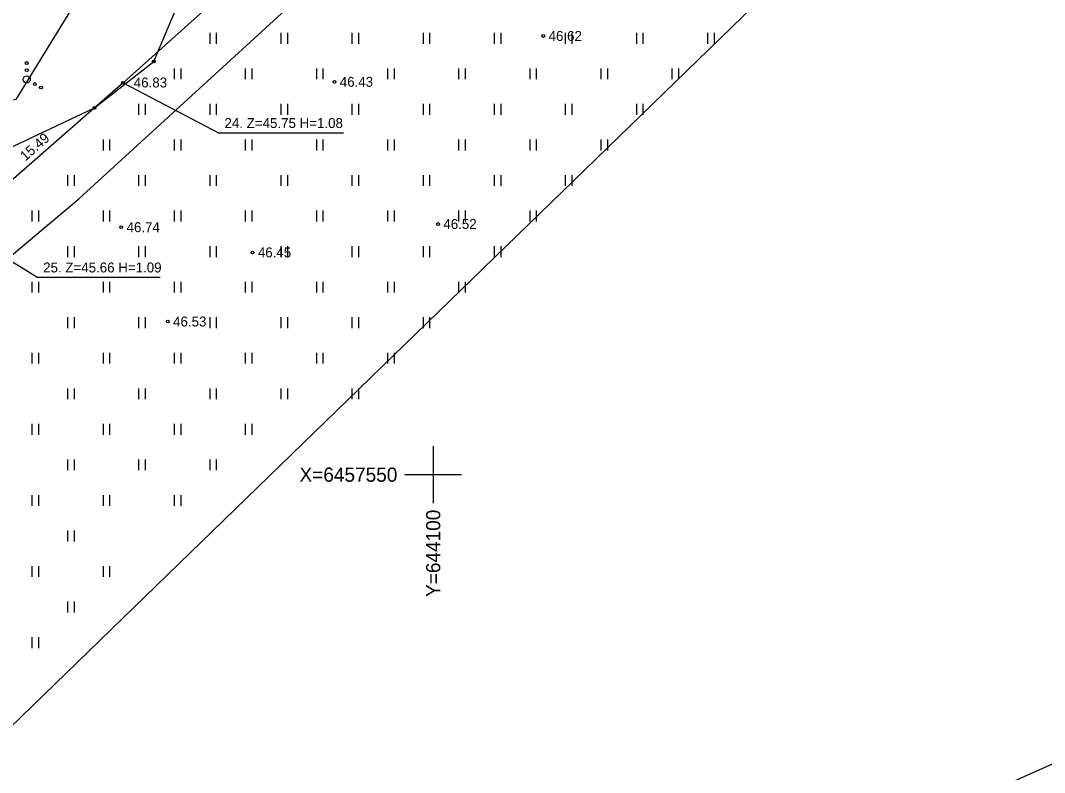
# Model space of a CAD drawing. Extents: x 642747 to 644424, y 6457048 to 6458238.
# Drawn here: x 644071 to 644143, y 6457529.1 to 6457581.9 of the extents above; entities that cross this region are included whole.
import ezdxf

# ---------------------------------------------------------------- set-up
doc = ezdxf.new("R2010")
doc.units = 0
for name, color, linetype in [('HALJASTUS', 7, 'Continuous'), ('JOONSIDE', 7, 'Continuous'), ('KOORDPUNKT', 7, 'Continuous'), ('KORGUS', 7, 'Continuous'), ('KPKAABEL', 7, 'Continuous'), ('MOOTPIIR', 7, 'Continuous'), ('TEE', 7, 'Continuous'), ('VORK', 7, 'Continuous'), ('VORMISTUS', 7, 'Continuous')]:
    doc.layers.add(name, color=color, linetype=linetype)

msp = doc.modelspace()

# ---------------------------------------------------------------- linework, layer by layer
at = {"layer": 'HALJASTUS'}
for p, q in [((644084.29, 6457581.069), (644084.29, 6457580.307)), ((644084.745, 6457581.069), (644084.745, 6457580.307)), ((644089.29, 6457581.069), (644089.29, 6457580.307)), ((644089.745, 6457581.069), (644089.745, 6457580.307)), ((644094.29, 6457581.069), (644094.29, 6457580.307)), ((644094.745, 6457581.069), (644094.745, 6457580.307)), ((644099.29, 6457581.069), (644099.29, 6457580.307)), ((644099.745, 6457581.069), (644099.745, 6457580.307)), ((644104.29, 6457581.069), (644104.29, 6457580.307)), ((644104.745, 6457581.069), (644104.745, 6457580.307)), ((644109.29, 6457581.069), (644109.29, 6457580.307)), ((644109.745, 6457581.069), (644109.745, 6457580.307)), ((644114.29, 6457581.069), (644114.29, 6457580.307)), ((644114.745, 6457581.069), (644114.745, 6457580.307)), ((644119.29, 6457581.069), (644119.29, 6457580.307)), ((644119.745, 6457581.069), (644119.745, 6457580.307)), ((644081.79, 6457578.569), (644081.79, 6457577.807)), ((644082.245, 6457578.569), (644082.245, 6457577.807)), ((644086.79, 6457578.569), (644086.79, 6457577.807)), ((644087.245, 6457578.569), (644087.245, 6457577.807)), ((644091.79, 6457578.569), (644091.79, 6457577.807)), ((644092.245, 6457578.569), (644092.245, 6457577.807)), ((644096.79, 6457578.569), (644096.79, 6457577.807)), ((644097.245, 6457578.569), (644097.245, 6457577.807)), ((644101.79, 6457578.569), (644101.79, 6457577.807)), ((644102.245, 6457578.569), (644102.245, 6457577.807)), ((644106.79, 6457578.569), (644106.79, 6457577.807)), ((644107.245, 6457578.569), (644107.245, 6457577.807)), ((644111.79, 6457578.569), (644111.79, 6457577.807)), ((644112.245, 6457578.569), (644112.245, 6457577.807)), ((644116.79, 6457578.569), (644116.79, 6457577.807)), ((644117.245, 6457578.569), (644117.245, 6457577.807)), ((644079.29, 6457576.069), (644079.29, 6457575.307)), ((644079.745, 6457576.069), (644079.745, 6457575.307)), ((644084.29, 6457576.069), (644084.29, 6457575.307)), ((644084.745, 6457576.069), (644084.745, 6457575.307)), ((644089.29, 6457576.069), (644089.29, 6457575.307)), ((644089.745, 6457576.069), (644089.745, 6457575.307)), ((644094.29, 6457576.069), (644094.29, 6457575.307)), ((644094.745, 6457576.069), (644094.745, 6457575.307)), ((644099.29, 6457576.069), (644099.29, 6457575.307)), ((644099.745, 6457576.069), (644099.745, 6457575.307)), ((644104.29, 6457576.069), (644104.29, 6457575.307)), ((644104.745, 6457576.069), (644104.745, 6457575.307)), ((644109.29, 6457576.069), (644109.29, 6457575.307)), ((644109.745, 6457576.069), (644109.745, 6457575.307)), ((644114.29, 6457576.069), (644114.29, 6457575.307)), ((644114.745, 6457576.069), (644114.745, 6457575.307)), ((644076.79, 6457573.569), (644076.79, 6457572.807)), ((644077.245, 6457573.569), (644077.245, 6457572.807)), ((644081.79, 6457573.569), (644081.79, 6457572.807)), ((644082.245, 6457573.569), (644082.245, 6457572.807)), ((644086.79, 6457573.569), (644086.79, 6457572.807)), ((644087.245, 6457573.569), (644087.245, 6457572.807)), ((644091.79, 6457573.569), (644091.79, 6457572.807)), ((644092.245, 6457573.569), (644092.245, 6457572.807)), ((644096.79, 6457573.569), (644096.79, 6457572.807)), ((644097.245, 6457573.569), (644097.245, 6457572.807)), ((644101.79, 6457573.569), (644101.79, 6457572.807)), ((644102.245, 6457573.569), (644102.245, 6457572.807)), ((644106.79, 6457573.569), (644106.79, 6457572.807)), ((644107.245, 6457573.569), (644107.245, 6457572.807)), ((644111.79, 6457573.569), (644111.79, 6457572.807)), ((644112.245, 6457573.569), (644112.245, 6457572.807)), ((644074.29, 6457571.069), (644074.29, 6457570.307)), ((644074.745, 6457571.069), (644074.745, 6457570.307)), ((644079.29, 6457571.069), (644079.29, 6457570.307)), ((644079.745, 6457571.069), (644079.745, 6457570.307)), ((644084.29, 6457571.069), (644084.29, 6457570.307)), ((644084.745, 6457571.069), (644084.745, 6457570.307)), ((644089.29, 6457571.069), (644089.29, 6457570.307)), ((644089.745, 6457571.069), (644089.745, 6457570.307)), ((644094.29, 6457571.069), (644094.29, 6457570.307)), ((644094.745, 6457571.069), (644094.745, 6457570.307)), ((644099.29, 6457571.069), (644099.29, 6457570.307)), ((644099.745, 6457571.069), (644099.745, 6457570.307)), ((644104.29, 6457571.069), (644104.29, 6457570.307)), ((644104.745, 6457571.069), (644104.745, 6457570.307)), ((644109.29, 6457571.069), (644109.29, 6457570.307)), ((644109.745, 6457571.069), (644109.745, 6457570.307)), ((644071.79, 6457568.569), (644071.79, 6457567.807)), ((644072.245, 6457568.569), (644072.245, 6457567.807)), ((644076.79, 6457568.569), (644076.79, 6457567.807)), ((644077.245, 6457568.569), (644077.245, 6457567.807)), ((644081.79, 6457568.569), (644081.79, 6457567.807)), ((644082.245, 6457568.569), (644082.245, 6457567.807)), ((644086.79, 6457568.569), (644086.79, 6457567.807)), ((644087.245, 6457568.569), (644087.245, 6457567.807)), ((644091.79, 6457568.569), (644091.79, 6457567.807)), ((644092.245, 6457568.569), (644092.245, 6457567.807)), ((644096.79, 6457568.569), (644096.79, 6457567.807)), ((644097.245, 6457568.569), (644097.245, 6457567.807)), ((644101.79, 6457568.569), (644101.79, 6457567.807)), ((644102.245, 6457568.569), (644102.245, 6457567.807)), ((644106.79, 6457568.569), (644106.79, 6457567.807)), ((644107.245, 6457568.569), (644107.245, 6457567.807)), ((644074.29, 6457566.069), (644074.29, 6457565.307)), ((644074.745, 6457566.069), (644074.745, 6457565.307)), ((644079.29, 6457566.069), (644079.29, 6457565.307)), ((644079.745, 6457566.069), (644079.745, 6457565.307)), ((644084.29, 6457566.069), (644084.29, 6457565.307)), ((644084.745, 6457566.069), (644084.745, 6457565.307)), ((644089.29, 6457566.069), (644089.29, 6457565.307)), ((644089.745, 6457566.069), (644089.745, 6457565.307)), ((644094.29, 6457566.069), (644094.29, 6457565.307)), ((644094.745, 6457566.069), (644094.745, 6457565.307)), ((644099.29, 6457566.069), (644099.29, 6457565.307)), ((644099.745, 6457566.069), (644099.745, 6457565.307)), ((644104.29, 6457566.069), (644104.29, 6457565.307)), ((644104.745, 6457566.069), (644104.745, 6457565.307)), ((644071.79, 6457563.569), (644071.79, 6457562.807)), ((644072.245, 6457563.569), (644072.245, 6457562.807)), ((644076.79, 6457563.569), (644076.79, 6457562.807)), ((644077.245, 6457563.569), (644077.245, 6457562.807)), ((644081.79, 6457563.569), (644081.79, 6457562.807)), ((644082.245, 6457563.569), (644082.245, 6457562.807)), ((644086.79, 6457563.569), (644086.79, 6457562.807)), ((644087.245, 6457563.569), (644087.245, 6457562.807)), ((644091.79, 6457563.569), (644091.79, 6457562.807)), ((644092.245, 6457563.569), (644092.245, 6457562.807)), ((644096.79, 6457563.569), (644096.79, 6457562.807)), ((644097.245, 6457563.569), (644097.245, 6457562.807)), ((644101.79, 6457563.569), (644101.79, 6457562.807)), ((644102.245, 6457563.569), (644102.245, 6457562.807)), ((644074.29, 6457561.069), (644074.29, 6457560.307)), ((644074.745, 6457561.069), (644074.745, 6457560.307)), ((644079.29, 6457561.069), (644079.29, 6457560.307)), ((644079.745, 6457561.069), (644079.745, 6457560.307)), ((644084.29, 6457561.069), (644084.29, 6457560.307)), ((644084.745, 6457561.069), (644084.745, 6457560.307)), ((644089.29, 6457561.069), (644089.29, 6457560.307)), ((644089.745, 6457561.069), (644089.745, 6457560.307)), ((644094.29, 6457561.069), (644094.29, 6457560.307)), ((644094.745, 6457561.069), (644094.745, 6457560.307)), ((644099.29, 6457561.069), (644099.29, 6457560.307)), ((644099.745, 6457561.069), (644099.745, 6457560.307)), ((644071.79, 6457558.569), (644071.79, 6457557.807)), ((644072.245, 6457558.569), (644072.245, 6457557.807)), ((644076.79, 6457558.569), (644076.79, 6457557.807)), ((644077.245, 6457558.569), (644077.245, 6457557.807)), ((644081.79, 6457558.569), (644081.79, 6457557.807)), ((644082.245, 6457558.569), (644082.245, 6457557.807)), ((644086.79, 6457558.569), (644086.79, 6457557.807)), ((644087.245, 6457558.569), (644087.245, 6457557.807)), ((644091.79, 6457558.569), (644091.79, 6457557.807)), ((644092.245, 6457558.569), (644092.245, 6457557.807)), ((644096.79, 6457558.569), (644096.79, 6457557.807)), ((644097.245, 6457558.569), (644097.245, 6457557.807)), ((644074.29, 6457556.069), (644074.29, 6457555.307)), ((644074.745, 6457556.069), (644074.745, 6457555.307)), ((644079.29, 6457556.069), (644079.29, 6457555.307)), ((644079.745, 6457556.069), (644079.745, 6457555.307)), ((644084.29, 6457556.069), (644084.29, 6457555.307)), ((644084.745, 6457556.069), (644084.745, 6457555.307)), ((644089.29, 6457556.069), (644089.29, 6457555.307)), ((644089.745, 6457556.069), (644089.745, 6457555.307)), ((644094.29, 6457556.069), (644094.29, 6457555.307)), ((644094.745, 6457556.069), (644094.745, 6457555.307)), ((644071.79, 6457553.569), (644071.79, 6457552.807)), ((644072.245, 6457553.569), (644072.245, 6457552.807)), ((644076.79, 6457553.569), (644076.79, 6457552.807)), ((644077.245, 6457553.569), (644077.245, 6457552.807)), ((644081.79, 6457553.569), (644081.79, 6457552.807)), ((644082.245, 6457553.569), (644082.245, 6457552.807)), ((644086.79, 6457553.569), (644086.79, 6457552.807)), ((644087.245, 6457553.569), (644087.245, 6457552.807)), ((644074.29, 6457551.069), (644074.29, 6457550.307)), ((644074.745, 6457551.069), (644074.745, 6457550.307)), ((644079.29, 6457551.069), (644079.29, 6457550.307)), ((644079.745, 6457551.069), (644079.745, 6457550.307)), ((644084.29, 6457551.069), (644084.29, 6457550.307)), ((644084.745, 6457551.069), (644084.745, 6457550.307)), ((644071.79, 6457548.569), (644071.79, 6457547.807)), ((644072.245, 6457548.569), (644072.245, 6457547.807)), ((644076.79, 6457548.569), (644076.79, 6457547.807)), ((644077.245, 6457548.569), (644077.245, 6457547.807)), ((644081.79, 6457548.569), (644081.79, 6457547.807)), ((644082.245, 6457548.569), (644082.245, 6457547.807)), ((644074.29, 6457546.069), (644074.29, 6457545.307)), ((644074.745, 6457546.069), (644074.745, 6457545.307)), ((644071.79, 6457543.569), (644071.79, 6457542.807)), ((644072.245, 6457543.569), (644072.245, 6457542.807)), ((644076.79, 6457543.569), (644076.79, 6457542.807)), ((644077.245, 6457543.569), (644077.245, 6457542.807)), ((644074.29, 6457541.069), (644074.29, 6457540.307)), ((644074.745, 6457541.069), (644074.745, 6457540.307)), ((644071.79, 6457538.569), (644071.79, 6457537.807)), ((644072.245, 6457538.569), (644072.245, 6457537.807))]:
    msp.add_line(p, q, dxfattribs=at)
msp.add_lwpolyline([(644041.809, 6457571.148), (644051.359, 6457564.407), (644056.959, 6457566.734), (644063.59, 6457569.91), (644069.17, 6457572.488), (644076.19, 6457575.794), (644080.356, 6457579.056), (644082.641, 6457584.464), (644086.464, 6457590.743), (644093.515, 6457598.78), (644095.215, 6457603.14), (644095.047, 6457607.095)], dxfattribs=at)
for centre, radius in [((644071.422, 6457578.949), 0.1), ((644071.422, 6457577.799), 0.25), ((644071.422, 6457578.449), 0.1), ((644071.987, 6457577.474), 0.1), ((644072.422, 6457577.224), 0.1)]:
    msp.add_circle(centre, radius, dxfattribs=at)
at = {"layer": 'KOORDPUNKT'}
for p, q in [((644078.192, 6457577.561), (644084.942, 6457574.027)), ((644093.691, 6457574.027), (644084.942, 6457574.027)), ((644066.524, 6457567.369), (644072.19, 6457563.871)), ((644080.799, 6457563.871), (644072.19, 6457563.871))]:
    msp.add_line(p, q, dxfattribs=at)
msp.add_lwpolyline([(644078.192, 6457577.561), (644078.192, 6457577.561), (644078.192, 6457577.561)], dxfattribs=at)
at = {"layer": 'KORGUS'}
for centre in [(644107.738, 6457580.854), (644080.356, 6457579.056), (644078.192, 6457577.561), (644093.057, 6457577.629), (644076.19, 6457575.794), (644078.065, 6457567.404), (644100.342, 6457567.628), (644087.299, 6457565.629), (644081.337, 6457560.771)]:
    msp.add_circle(centre, 0.1, dxfattribs=at)
at = {"layer": 'KPKAABEL'}
msp.add_lwpolyline([(644103.079, 6457652.715), (644111.131, 6457630.665), (644117.872, 6457612.305), (644117.831, 6457611.89), (644117.527, 6457611.592), (644112.751, 6457607.616), (644102.693, 6457600.124), (644092.698, 6457590.582), (644078.192, 6457577.561), (644066.524, 6457567.369), (644056.896, 6457559.139), (644048.865, 6457552.537), (644048.039, 6457551.927), (644047.155, 6457551.979), (644039.639, 6457557.844), (644029.553, 6457566.384), (644016.901, 6457577.396), (644002.145, 6457590.823), (643989.718, 6457602.415), (643976.894, 6457615.305), (643965.556, 6457626.702)], dxfattribs=at)
at = {"layer": 'MOOTPIIR'}
msp.add_lwpolyline([(643525.446, 6457467.559), (643537.447, 6457435.458), (643944.848, 6457628.51), (644046.626, 6457529.09), (644067.022, 6457529.09), (644138.408, 6457598.401), (644075.1, 6457775.215), (644046.02, 6457752.582), (644092.466, 6457611.94), (644070.657, 6457576.375), (644041.981, 6457570.717), (643942.223, 6457662.862)], close=True, dxfattribs=at)
at = {"layer": 'TEE'}
msp.add_lwpolyline([(644051.619, 6457549.694), (644075.076, 6457569.399), (644100.273, 6457592.468), (644111.741, 6457604.69), (644121.185, 6457609.883)], dxfattribs=at)
at = {"layer": 'VORK'}
for p, q in [((644100, 6457552), (644100, 6457548)), ((644098, 6457550), (644102, 6457550))]:
    msp.add_line(p, q, dxfattribs=at)
at = {"layer": 'VORMISTUS'}
msp.add_line((644015.847, 6457472.946), (644180.435, 6457546.05), dxfattribs=at)

# ---------------------------------------------------------------- texts
at = {"layer": 'JOONSIDE'}
msp.add_text('15.49', height=0.7, rotation=41.13722, dxfattribs=at).set_placement((644071.324, 6457572.023))
at = {"layer": 'KOORDPUNKT'}
for s, p in [('24. Z=45.75 H=1.08', (644085.327, 6457574.377)), ('25. Z=45.66 H=1.09', (644072.575, 6457564.221))]:
    msp.add_text(s, height=0.7, dxfattribs=at).set_placement(p)
at = {"layer": 'KORGUS'}
for s, p in [('46.62', (644108.113, 6457580.504)), ('46.83', (644078.947, 6457577.231)), ('46.43', (644093.432, 6457577.279)), ('46.74', (644078.44, 6457567.054)), ('46.52', (644100.717, 6457567.278)), ('46.45', (644087.674, 6457565.279)), ('46.53', (644081.712, 6457560.421))]:
    msp.add_text(s, height=0.7, dxfattribs=at).set_placement(p)
at = {"layer": 'VORK'}
msp.add_text('X=6457550     ', height=1, dxfattribs=at).set_placement((644090.601, 6457549.5))
msp.add_text('Y=644100     ', height=1, rotation=90, dxfattribs=at).set_placement((644100.5, 6457541.401))

doc.saveas('drawing.dxf')
